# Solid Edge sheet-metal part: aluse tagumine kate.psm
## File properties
Title: aluse tagumine kate
Author: Stella-Marii
Template: Iso Metric Sheet Metal.psm
Last saved by: Stella-Marii
Revision: 10
Application: Solid Edge
Document Number: 12
Density: 7833,000 kg/m^3
Accuracy: 0,990
Material Thickness: 3,00 mm
Bend Radius: 1,00 mm
Relief Width: 1,00 mm
Relief Length: 0,00 mm
Neutral Factor: 0,330
Minimum Arc Length: 0,10 mm
Deviational Tolerance: 0,10 mm
Username: Stella-Marii
Material: Steel, structural
Face Style: Steel
Fill Style: ANSI32(Steel)
Virtual Style: Brushed steel
Grouping: Metals\Steel
LibraryName: Materials
Coef. of Thermal Exp: 1.3e-05
Thermal Conductivity: 32.0
Specific Heat: 481.0
Modulus of Elasticity: 199947953000.0
Poisson's Ratio: 0.29
Yield Stress: 262000766.0
Ultimate Stress: 358527364.0
Elongation: 0.0
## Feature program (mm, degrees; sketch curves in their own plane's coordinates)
base tab "unnamed BaseTab 1"
break corner "BreakCorner_1"  SetBackValue1 = 40 mm
jog tab "JogTab_1"  OffsetDistance = 4 mm
sheet metal cutout "SheetMetalCutout_1"
break corner "BreakCorner_2"  SetBackValue1 = 2 mm
break corner "BreakCorner_3"  SetBackValue1 = 5 mm
break corner "BreakCorner_4"  SetBackValue1 = 1 mm
mirror "unnamed Mirror 1" of "BreakCorner_4", "SheetMetalCutout_1", "BreakCorner_2", "BreakCorner_3"
pattern "unnamed Pattern 1"
dimple "Dimple_1"
pattern "unnamed Pattern 2" of "Dimple_1"
pattern "unnamed Pattern 3"
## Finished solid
Body 1: solid body, 264 faces, 302 edges, 40 vertices.
  Faces by surface: plane 92, cylinder 90, torus 80, spline 2
  Edges by curve: circle 260, line 38, intersection 4
Bounding box of the edges (mm; curved faces can reach further): 300.000 x 215.000 x 10.500, from (-150, -107.5, -3.5) to (150, 107.5, 7).
Cylindrical faces by radius (mm): R1 x2, R2 x42, R4 x2, R5 x42, R40 x2
Toroidal faces (ring radius, tube radius in mm): R2 r3 x40, R5 r3 x40
Planar faces by outward normal: +x 2, +y 1, +z 42, -x 2, -y 3, -z 42
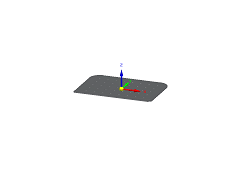
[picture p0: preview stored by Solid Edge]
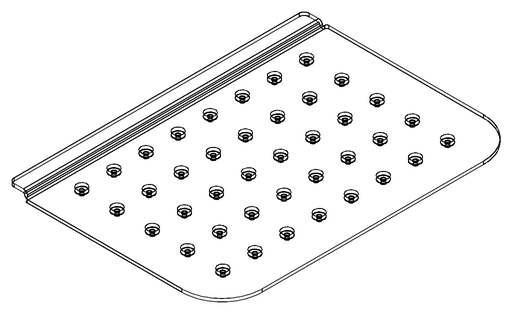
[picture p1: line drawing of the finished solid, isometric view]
